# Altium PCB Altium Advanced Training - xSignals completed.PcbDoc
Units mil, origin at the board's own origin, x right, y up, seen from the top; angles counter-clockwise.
Board outline 4055.12 x 2100 mil, 3 copper layers (Top Layer, GND, Bottom Layer), stack 68.617 mil thick; 14 components, 11 nets, 32 pads, 2 vias.
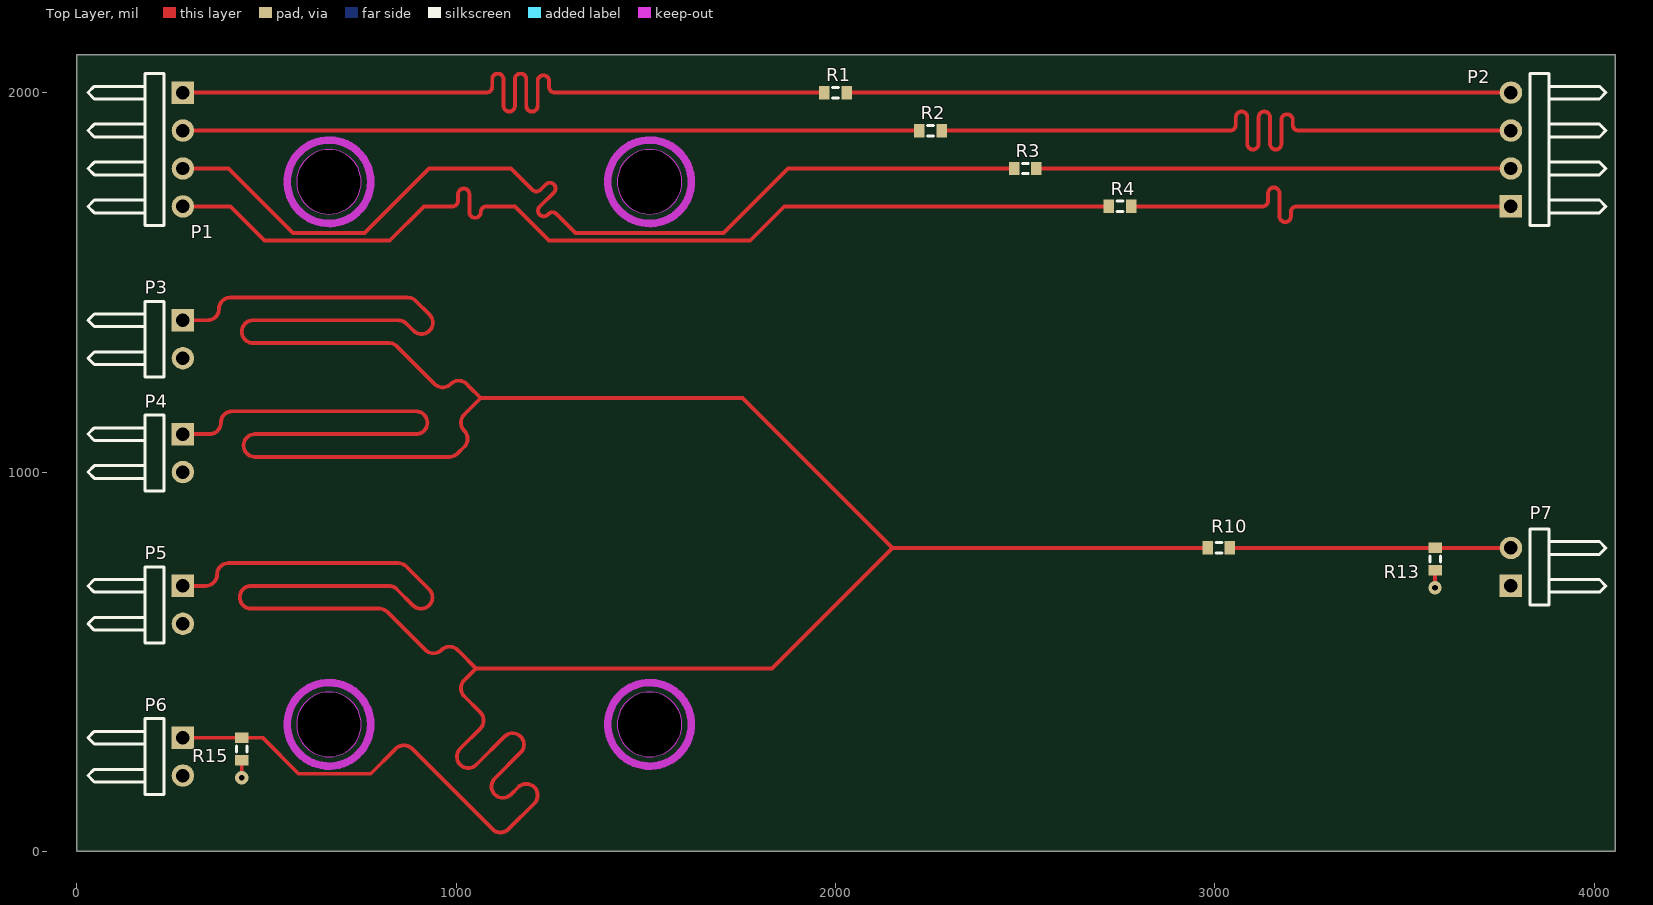
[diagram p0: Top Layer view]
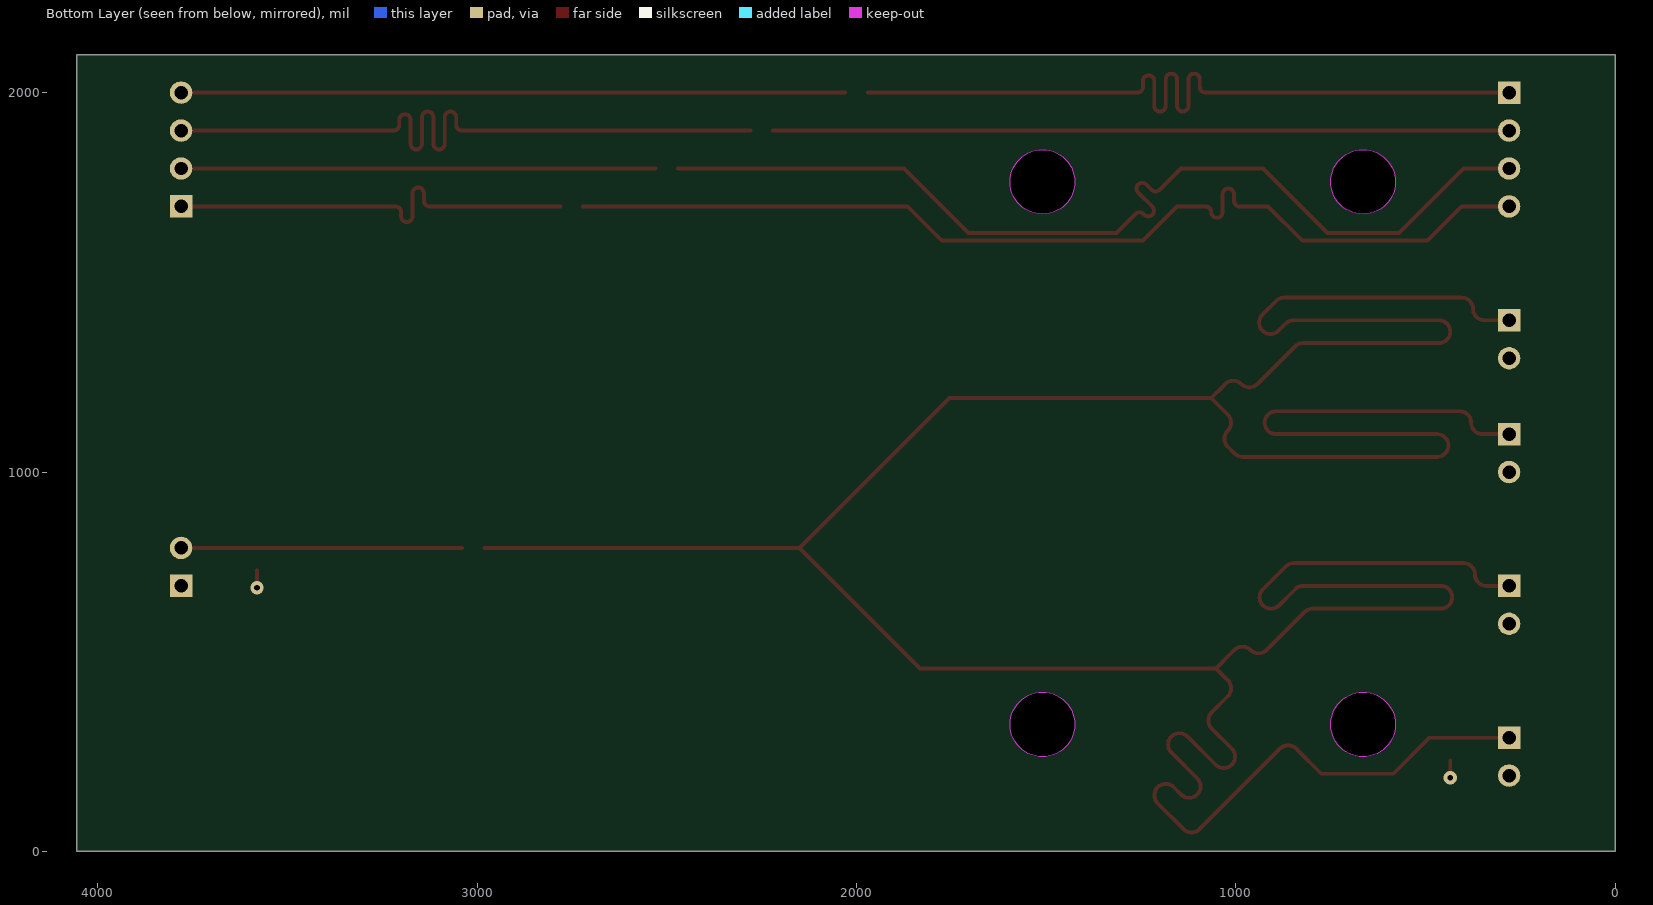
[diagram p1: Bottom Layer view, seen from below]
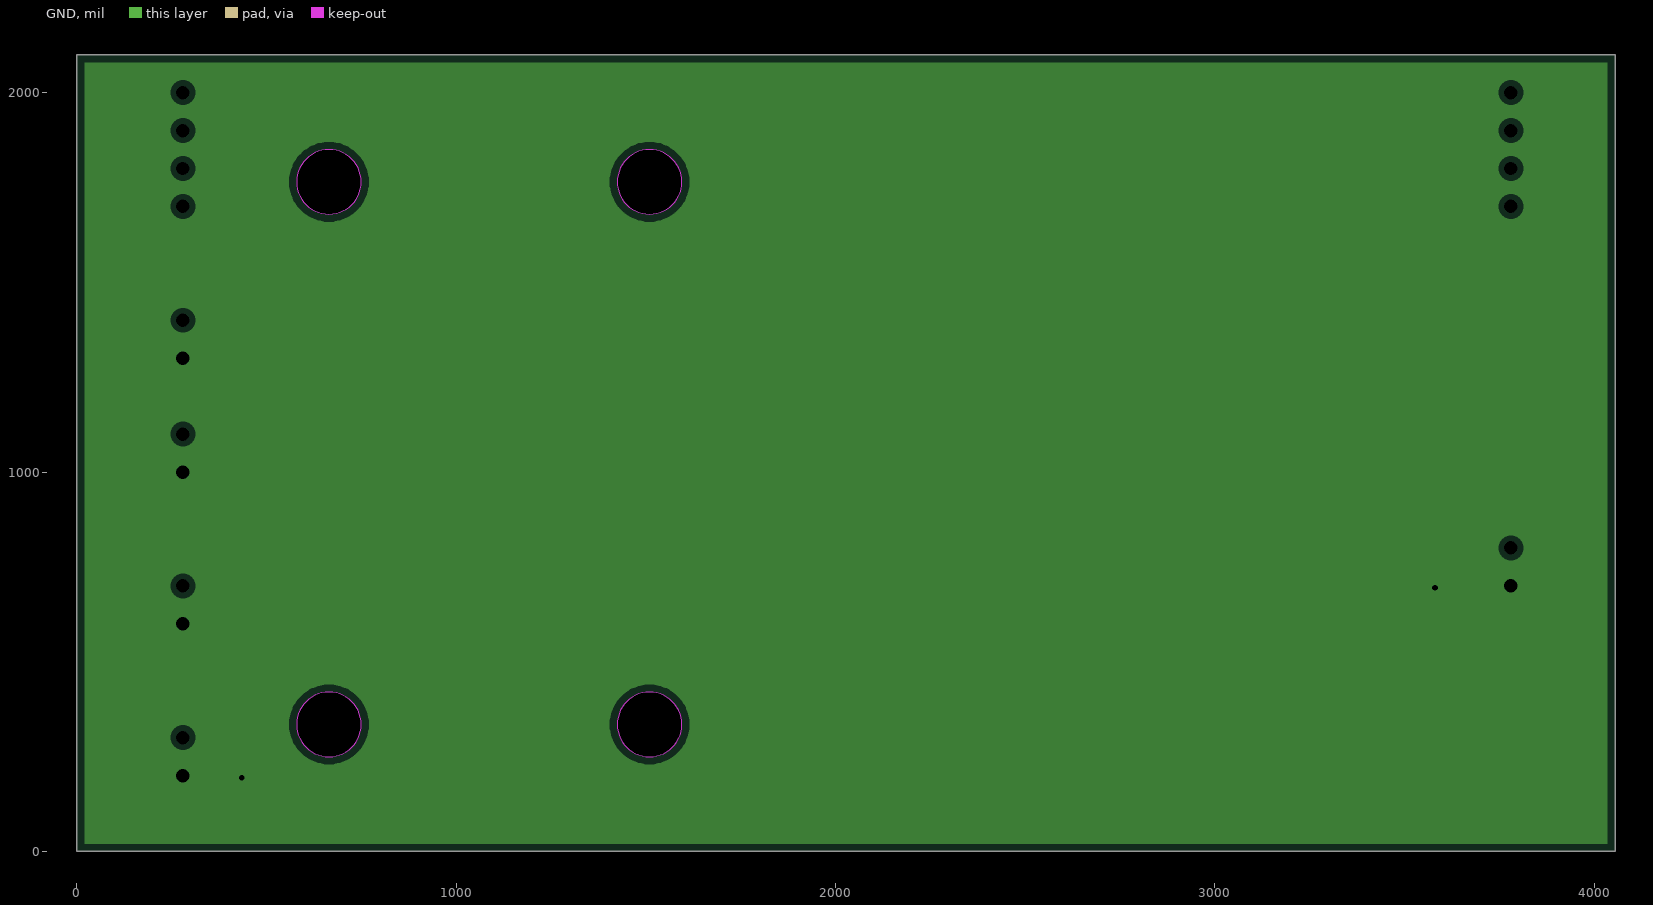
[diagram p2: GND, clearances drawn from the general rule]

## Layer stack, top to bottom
Top Solder: solder mask 0.4, Solder Resist, Dk 3.5
Top Layer: signal copper 1.4
Dielectric1: core 59.4, FR-4, Dk 4
GND: plane copper 1.417, net GND
Dielectric 2: prepreg 5, Dk 4.2
Bottom Layer: signal copper 1.4
Bottom Solder: solder mask 0.4, Solder Resist, Dk 3.5

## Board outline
0,0 4055.12,0 4055.12,2100 0,2100
cut-out: 579.65,334.79 ccw(c664.79,334.79) 664.79,249.65 ccw(c664.79,334.79) 749.94,334.79 ccw(c664.79,334.79) 664.79,419.94 ccw(c664.79,334.79)
cut-out: 579.65,1764.79 ccw(c664.79,1764.79) 664.79,1679.65 ccw(c664.79,1764.79) 749.94,1764.79 ccw(c664.79,1764.79) 664.79,1849.94 ccw(c664.79,1764.79)
cut-out: 1424.65,334.79 ccw(c1509.79,334.79) 1509.79,249.65 ccw(c1509.79,334.79) 1594.94,334.79 ccw(c1509.79,334.79) 1509.79,419.94 ccw(c1509.79,334.79)
cut-out: 1424.65,1764.79 ccw(c1509.79,1764.79) 1509.79,1679.65 ccw(c1509.79,1764.79) 1594.94,1764.79 ccw(c1509.79,1764.79) 1509.79,1849.94 ccw(c1509.79,1764.79)

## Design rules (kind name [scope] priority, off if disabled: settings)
AcuteAngle [All] p1: minimum=5.50000000000000E+0001 checktracksonly=FALSE
AssemblyTestPointUsage [All] p1 off:
AssemblyTestpoint [All] p1 off: testpointundercomponent=TRUE minsize=40 maxsize=100 preferedsize=60 minholesize=0 maxholesize=40 preferedholesize=32 testpointgrid=1 usegrid=TRUE gridtolerance=0.01 allowsidetop=TRUE allowsidebottom=TRUE
BoardOutlineClearance [All] p1: gap=10 ignorepadtopadclearanceinfootprint=FALSE except(0: Arc-SplitContinuation Track-SplitContinuation SMDPad-SplitContinuation THPad-SplitContinuation Via-SplitContinuation Fill-SplitContinuation Poly-SplitContinuation Region-SplitContinuation Text-SplitContinuation)
Clearance [All] p1: gap=8 ignorepadtopadclearanceinfootprint=FALSE except(0: Arc-Hole Track-Hole SMDPad-Hole THPad-Hole Via-Hole Fill-Hole Poly-Hole Region-Hole Text-Hole)
FabricationTestPointUsage [All] p1 off: valid=0 allowmultiple=FALSE
FabricationTestpoint [(IsPad And (OnTopLayer Or OnBottomLayer))] p1 off: side=3 testpointundercomponent=TRUE minsize=40 maxsize=100 preferedsize=60 minholesize=0 maxholesize=40 preferedholesize=32 testpointgrid=1 allowsidetop=TRUE allowsidebottom=TRUE usegrid=TRUE gridtolerance=0.01
Height [All] p1: minheight=0 maxheight=1500 prefheight=500
HoleSize [All] p1: absolutevalues=TRUE maxlimit=200 minlimit=10 maxpercent=80.000 minpercent=20.000
HoleToHoleClearance [All] p1: gap=1 allowstackedmicrovias=FALSE
Length Length_TJunct [InxSignalClass('xSignals_R10_P3,P4,P5,P6')] p1: maxlimit=4100 minlimit=3900
Length Length_Series-Term [InxSignalClass('Series-Term')] p2: maxlimit=3855 minlimit=3845
MatchedLengths MatchLengths_xSignals_R10_P3,P4,P5,P6 [InxSignalClass('xSignals_R10_P3,P4,P5,P6_MatchLengthsClass')] p1: tolerance=20 checknetsindiffpair=FALSE checkdiffpairvsdiffpair=TRUE checkxsignals=TRUE checkothers=TRUE
MinimumAnnularRing [All] p1: minimumring=5
MinimumSolderMaskSliver [All] p1: minsoldermaskwidth=3
NetAntennae [All] p1: netantennaetolerance=5
PlaneClearance [All] p1: clearance=15
PlaneConnect [All] p1: planeconnectstyle=Relief reliefexpansion=15 reliefentries=4 reliefconductorwidth=8 reliefairgap=8
PolygonConnect [All] p1: connectstyle=Relief reliefconductorwidth=8 reliefentries=4 polygonreliefangle="90 Angle" airgapwidth=10
RoutingTopology RoutingTopology_TJUNCT [InNet('TJUNCT')] p1: topology=Starburst
RoutingTopology [All] p2: topology=Shortest
RoutingVias [All] p1: holewidth=10 width=20 viastyle="Through Hole" minholewidth=10 minwidth=20 maxholewidth=30 maxwidth=40
SilkToSilkClearance [All] p1: silktosilkclearance=1
SilkToSolderMaskClearance SilkscreenOverComponentPads [IsPad] p1: minsilkscreentomaskgap=2 clearancetoexposedcopper=TRUE
SolderMaskExpansion [All] p1: expansion=1 istentingtop=FALSE
Width [All] p1: maxlimit=200 minlimit=8 preferedwidth=10
16 further rules are at their usual default settings.

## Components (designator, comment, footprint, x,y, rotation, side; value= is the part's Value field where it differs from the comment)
P1 "Header 4H" HDR1X4H 280,2000 r270 top
P2 "Header 4H" HDR1X4H 3780,1700 r90 top
P3 "Header 2H" HDR1X2H 280,1400 r270 top
P4 "Header 2H" HDR1X2H 280,1100 r270 top
P5 "Header 2H" HDR1X2H 280,700 r270 top
P6 "Header 2H" HDR1X2H 280,300 r270 top
P7 "Header 2H" HDR1X2H 3780,700 r90 top
R1 "Res3" J1-0603 2000,2000 r180 top
R2 "Res3" J1-0603 2250,1900 r180 top
R3 "Res3" J1-0603 2500,1800 r180 top
R4 "Res3" J1-0603 2750,1700 r180 top
R10 "Res3" J1-0603 3010,800 r180 top
R13 "Res3" J1-0603 3580,770.47 r90 top
R15 "Res3" J1-0603 435,270 r90 top

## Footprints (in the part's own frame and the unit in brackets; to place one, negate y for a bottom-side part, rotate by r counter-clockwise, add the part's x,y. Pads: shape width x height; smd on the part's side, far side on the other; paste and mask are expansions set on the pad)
HDR1X2H [mm] "Connector; Header; 2 Position; Right Angle"
  rect 1.5x1.5 hole 0.9: 1(0,0)
  round 1.5 hole 0.9: 2(2.54,0)
  silkscreen extent -1.27,-6.35 3.81,-1.27
HDR1X4H [mm] "Connector; Header; 4 Position; Right Angle"
  rect 1.5x1.5 hole 0.9: 1(0,0)
  round 1.5 hole 0.9: 2(2.54,0) 3(5.08,0) 4(7.62,0)
  silkscreen extent -1.27,-6.35 8.89,-1.27
J1-0603 [mm] "Chip Resistor, Body 1.6x0.8mm, IPC High Density"
  rect 0.7x0.9 smd: 1(-0.75,0) 2(0.75,0)
  silkscreen extent -0.2,-0.35 0.2,0.35, body extent -0.85,-0.48 0.85,0.48, height 0.9

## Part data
P1 P2: "Header, 4-Pin, Right Angle"
P3 P4 P5 P6 P7: "Header, 2-Pin, Right Angle"
R1 R2 R3 R4 R10 R13 R15: "Resistor"

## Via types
v1: diameter 35, hole 15, Top Layer to Bottom Layer, 2 vias

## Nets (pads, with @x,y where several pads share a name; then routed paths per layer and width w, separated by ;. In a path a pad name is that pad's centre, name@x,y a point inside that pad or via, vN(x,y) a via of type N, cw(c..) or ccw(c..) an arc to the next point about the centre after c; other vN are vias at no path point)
BUS1: P1.1 R1.2 | length 2104.5
  Top Layer w10: P1.1 1050,2000 1075,2000 1080,2000 ccw(c1080,2015) 1095,2015 1095,2035 cw(c1110,2035) 1125,2035 1125,1965 ccw(c1140,1965) 1155,1965 1155,2035 cw(c1170,2035) 1185,2035 1185,1965 ccw(c1200,1965) 1215,1965 1215,2030.66 cw(c1230,2030.66) 1245,2030.66 1245,2015 ccw(c1260,2015) 1260,2000 1565,2000 1569.77,2000 R1.2
BUS2: P1.2 R2.2 | length 1940.5
  Top Layer w10: P1.2 R2.2
BUS3: P1.3 R3.2 | length 2599.5
  Top Layer w10: P1.3 400,1800 570,1630 758.75,1630 928.75,1800 1145,1800 1197.5,1747.5 1201.04,1743.96 ccw(c1211.64,1754.57) 1222.25,1743.96 1236.39,1758.11 cw(c1247,1747.5) 1257.6,1758.11 cw(c1247,1747.5) 1257.6,1736.89 1220.12,1699.41 ccw(c1230.73,1688.8) 1220.12,1678.2 ccw(c1230.73,1688.8) 1241.33,1678.2 1243.46,1680.32 cw(c1254.07,1669.72) 1264.68,1680.32 1315,1630 1705,1630 1875,1800 1937.5,1800 2235,1800 2285,1800 R3.2
BUS4: P1.4 R4.2 | length 2705.6
  Top Layer w10: P1.4 405,1700 495,1610 825,1610 915,1700 985,1700 990,1700 ccw(c990,1715) 1005,1715 1005,1732.3 cw(c1020,1732.3) 1035,1732.3 1035,1685 ccw(c1050,1685) 1065,1685 cw(c1080,1685) 1080,1700 1149.63,1700 1155,1700 1245,1610 1775,1610 1865,1700 R4.2
GND: P3.2 P4.2 P5.2 P6.2 P7.1 R13.1 R15.1 | length 91.9
  Top Layer w10: v1(435,194.53) R15.1 ; v1(3580,695) R13.1
OBUS1: P2.4 R1.1 | length 1750.5
  Top Layer w10: R1.1 2897.82,2000 P2.4
OBUS2: P2.3 R2.1 | length 1909.5
  Top Layer w10: R2.1 2540,1900 2720,1900 3035,1900 3040,1900 ccw(c3040,1915) 3055,1915 3055,1935 cw(c3070,1935) 3085,1935 3085,1865 ccw(c3100,1865) 3115,1865 3115,1935 cw(c3130,1935) 3145,1935 3145,1865 ccw(c3160,1865) 3175,1865 3175,1928.16 cw(c3190,1928.16) 3205,1928.16 3205,1915 ccw(c3220,1915) 3220,1900 3395,1900 P2.3
OBUS3: P2.2 R3.1 | length 1250.5
  Top Layer w10: R3.1 P2.2
OBUS4: P2.1 R4.1 | length 1144.4
  Top Layer w10: R4.1 3120,1700 3125,1700 ccw(c3125,1715) 3140,1715 3140,1735 cw(c3155,1735) 3170,1735 3170,1673.71 ccw(c3185,1673.71) 3200,1673.71 3200,1685 cw(c3215,1685) 3215,1700 3271.89,1700 3300,1700 P2.1
TJSOURCE: P7.2 R10.1 R13.2 | length 740.5
  Top Layer w10: R10.1 R13.2 P7.2
TJUNCT: P3.1 P4.1 P5.1 P6.1 R10.2 R15.2 | length 11285.9
  Top Layer w10: P6.1 434.53,300 R15.2 435.47,300 490,300 585,205 775,205 837.5,267.5 841.04,271.04 cw(c862.25,249.82) 883.46,271.04 1095.59,58.9 ccw(c1116.81,80.12) 1138.01,58.89 1206.01,126.89 ccw(c1184.8,148.11) 1206.01,169.32 ccw(c1184.8,148.11) 1163.58,169.32 1144.41,150.15 cw(c1123.2,171.36) 1101.98,150.15 cw(c1123.2,171.36) 1101.98,192.57 1169.96,260.55 ccw(c1148.74,281.76) 1169.96,302.97 ccw(c1148.74,281.76) 1127.53,302.97 1053.16,228.6 cw(c1031.95,249.82) 1010.73,271.02 1063.9,324.2 ccw(c1042.68,345.4) 1063.9,366.6 1021.46,409.04 cw(c1042.68,430.25) 1021.46,451.46 1025,455 1052.5,482.5 ; P5.1 335,700 340,700 ccw(c340,730) 370,730 cw(c400,730) 400,760 847.43,760 cw(c847.43,730) 868.63,751.23 928.88,690.97 cw(c907.67,669.76) 928.88,648.55 cw(c907.67,669.76) 886.45,648.55 843.77,691.23 ccw(c822.57,670) 822.57,700 460,700 ccw(c460,670) 430,670 ccw(c460,670) 460,640 797.72,640 cw(c797.72,610) 818.92,631.23 919.11,531.04 ccw(c940.32,552.25) 961.55,531.05 cw(c982.75,509.82) 1003.96,531.04 1007.5,527.5 1052.5,482.5 ; P4.1 345,1100 350,1100 ccw(c350,1130) 380,1130 cw(c410,1130) 410,1160 894.28,1160 cw(c894.28,1130) 924.28,1130 cw(c894.28,1130) 894.28,1100 470,1100 ccw(c470,1070) 440,1070 ccw(c470,1070) 470,1040 982.43,1040 ccw(c982.43,1070) 1003.63,1048.77 1021.48,1066.62 ccw(c1000.25,1087.82) 1021.43,1109.07 cw(c1042.68,1130.25) 1021.46,1151.46 1025,1155 1065,1195 ; P3.1 340,1400 345,1400 ccw(c345,1430) 375,1430 cw(c405,1430) 405,1460 872.43,1460 cw(c872.43,1430) 893.63,1451.23 930,1414.86 cw(c908.78,1393.64) 930,1372.43 cw(c908.78,1393.64) 887.57,1372.43 868.77,1391.23 ccw(c847.57,1370) 847.57,1400 465,1400 ccw(c465,1370) 435,1370 ccw(c465,1370) 465,1340 822.72,1340 cw(c822.72,1310) 843.92,1331.23 943.18,1231.96 ccw(c964.4,1253.18) 985.62,1231.98 cw(c1006.82,1210.75) 1028.04,1231.96 1031.57,1228.43 1065,1195 ; R10.2 2150,800 ; 1052.5,482.5 1832.5,482.5 2150,800 ; 1065,1195 1755,1195 2150,800

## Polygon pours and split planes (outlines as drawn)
GND on GND (split plane): 4035.02,20.1 20.1,20.1 20.1,2079.9 4035.02,2079.9

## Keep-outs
Top Layer:
  circle w20: c665,335 r110
  circle w20: c665,1765 r110
  circle w20: c1510,335 r110
  circle w20: c1510,1765 r110

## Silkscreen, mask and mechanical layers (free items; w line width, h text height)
Top Overlay:
  text "Altium Advanced Training: '.Pcb_File_Name_No_Path'" at 15,-251.68 h100
Mechanical 1:
  drawing of 211 lines, arcs and shapes, not listed
  text "Layer" at -5222.5,-212.5 h60
  text "Name" at -4874.26,-212.5 h60
  text "Material" at -4109.54,-212.5 h60
  text "Thickness" at -3447.08,-212.5 h60
  text "Constant" at -2933.16,-212.5 h60
  text "Board Layer Stack" at -2440.37,-212.5 h60
  text "Top Overlay" at -4874.26,-332.5 h60
  text "Top Solder" at -4874.26,-452.5 h60
  text "Solder Resist" at -4109.54,-452.5 h60
  text "0,40mil" at -3447.08,-452.5 h60
  text "3.5" at -2933.16,-452.5 h60
  text "1" at -5222.5,-572.5 h60
  text "Top Layer" at -4874.26,-572.5 h60
  text "1,40mil" at -3447.08,-572.5 h60
  text "Dielectric1" at -4874.26,-692.5 h60
  text "FR-4" at -4109.54,-692.5 h60
  text "59,40mil" at -3447.08,-692.5 h60
  text "4" at -2933.16,-692.5 h60
  text "2" at -5222.5,-812.5 h60
  text "GND" at -4874.26,-812.5 h60
  text "1,42mil" at -3447.08,-812.5 h60
  text "Dielectric 2" at -4874.26,-932.5 h60
  text "5,00mil" at -3447.08,-932.5 h60
  text "4.2" at -2933.16,-932.5 h60
  text "3" at -5222.5,-1052.5 h60
  text "Bottom Layer" at -4874.26,-1052.5 h60
  text "1,40mil" at -3447.08,-1052.5 h60
  text "Bottom Solder" at -4874.26,-1172.5 h60
  text "Solder Resist" at -4109.54,-1172.5 h60
  text "0,40mil" at -3447.08,-1172.5 h60
  text "3.5" at -2933.16,-1172.5 h60
  text "Bottom Overlay" at -4874.26,-1292.5 h60
Mechanical 16:
  lines w5: -5810.13,-1827.43 -5610.13,-1827.43 ; -5810.13,547.57 -5610.13,547.57 ; -5810.13,2922.57 -5610.13,2922.57 ; -3310.13,-4202.43 -3310.13,-4002.43 ; -3310.13,5097.57 -3310.13,5297.57 ; -810.13,-4202.43 -810.13,-4002.43 ; -810.13,5097.57 -810.13,5297.57 ; 1536.87,-4002.43 1536.87,-3207.43 ; 1689.87,-4202.43 1689.87,-4002.43 ; 1689.87,5097.57 1689.87,5297.57 ; 3089.87,-3207.43 1536.87,-3207.43 ; 3089.87,-2934.43 1536.87,-2934.43 1536.87,-3207.43 ; 4189.87,-4202.43 4189.87,-4002.43 ; 4189.87,5097.57 4189.87,5297.57 ; 4489.87,-3702.43 8989.87,-3702.43 ; 4489.87,-3402.43 8989.87,-3402.43 ; 4489.87,-3102.43 5989.87,-3102.43 ; 5989.72,-4002.28 5989.72,-3402.28 5989.72,-2802.28 8989.72,-2802.28 8989.72,-4002.28 ; 5989.87,-2802.43 4489.87,-2802.43 ; 6613.21,-4202.75 6613.21,-4002.75 ; 6689.87,-4202.43 6689.87,-4002.43 ; 6689.87,5097.57 6689.87,5297.57 ; 7259.72,-4002.28 7259.72,-3702.28 ; 8089.72,-4002.28 8089.72,-3402.28 ; 8989.87,-1827.43 9189.87,-1827.43 ; 8989.87,547.57 9189.87,547.57 ; 8989.87,2922.57 9189.87,2922.57 ; 4489.87,-4002.43 4489.87,-2802.43 ; 4489.87,-4002.43 8989.87,-4002.43 ; 4489.87,-4002.43 3089.87,-4002.43 3089.87,-2802.43 4489.87,-2802.43 ; 8989.87,-4002.43 8989.87,5097.57 -5610.13,5097.57 -5610.13,-4002.43 8989.87,-4002.43 ; -5810.13,-4202.43 -5810.13,5297.57 9189.87,5297.57 9189.87,-4202.43 -5810.13,-4202.43
  lines w10: 6539.87,4817.57 6539.87,4892.57 6539.87,4957.57 6539.87,5032.57 6539.87,5097.57 ; 6540,4817.57 8989.87,4817.57 ; 6540,4892.57 8989.87,4892.57 8989.87,5032.57 ; 6540,4957.57 8989.87,4957.57 ; 6540,5032.57 8989.87,5032.57 ; 6540,5097.57 8989.87,5097.57 8989.87,5032.57 ; 6684.87,4817.76 6684.87,5032.57 ; 7014.87,4817.76 7014.87,5032.57 ; 8419.87,4817.76 8419.87,5032.57 ; 8689.87,4817.76 8689.87,5032.57
  text "1" at -4578.79,5167.57 h70
  text "2" at -2083.13,5167.57 h70
  text "3" at 406.21,5167.57 h70
  text "4" at 2912.88,5167.57 h70
  text "5" at 5411.87,5167.57 h70
  text "6" at 7916.87,5167.57 h70
  text "REVISIONS" at 7642,5051.76 h30
  text "DESCRIPTION" at 7630,4980.76 h30
  text "REV" at 6564.87,4977.57 h30
  text "ECO#/ECR#" at 6724.87,4977.57 h30
  text "APPROV" at 8454.87,4977.57 h30
  text "DATE" at 8794.87,4977.57 h30
  text "01" at 6584.87,4912.57 h30
  text "INITIAL RELEASE" at 7054.87,4912.57 h30
  text "10/31/11" at 8734.87,4912.57 h30
  text "A" at -5735.13,4024.57 h70
  text "A" at 9064.87,4024.57 h70
  text "B" at -5735.13,1644.57 h70
  text "B" at 9064.87,1644.57 h70
  text "C" at -5735.13,-730.43 h70
  text "C" at 9064.87,-730.43 h70
  text "ENGINEER:" at 4539.87,-2902.43 h45
  text "TITLE:" at 6039.72,-2902.28 h45
  text "<YOUR NAME>" at 4646.87,-3053.43 h80
  text "Company" at 3158,-3074.24 h140
  text "D" at -5735.13,-3100.43 h70
  text "D" at 9064.87,-3100.43 h70
  text "PCB DESIGNER:" at 4539.87,-3197.43 h45
  text "UNLESS OTHERWISE SPECIFIED" at 1626.87,-3313.43 h55.31
  text "<YOUR NAME>" at 4644.87,-3376.43 h80
  text "DIMINSIONS ARE IN INCHES." at 1626.87,-3401.43 h55.31
  text "LAYER" at 6040.72,-3475.28 h45
  text "DATE:" at 4539.87,-3502.43 h45
  text "REV:" at 8139.72,-3502.28 h45
  text "TOLERANCES ARE:" at 1954.87,-3580.43 h55.31
  text ".PRINT_DATE" at 4589.87,-3622.43 h70
  text "01" at 8474.72,-3636.3 h130
  text "100 Main Street" at 3126.5,-3638.02 h56.25
  text "DECIMALS" at 1616.87,-3704.43 h55.31
  text "ANGLES" at 2576.87,-3720.43 h55.31
  text "AnytownUSA, CA 12345" at 3124.37,-3734.35 h56.25
  text "SHT NO:" at 7280.72,-3792.28 h45
  text ".XX  +/- .01" at 1612.87,-3800.43 h55.31
  text "FILE NAME:" at 4539.87,-3802.43 h45
  text "DWG NO:" at 6039.72,-3802.28 h45
  text "SCALE:" at 8139.72,-3802.28 h45
  text "+/- .5 DEG" at 2456.87,-3817.43 h55.31
  text "Phone: (123) 555-1212" at 3122.21,-3832.82 h55.31
  text ".XXX +/- .003" at 1612.87,-3906.43 h55.31
  text "name@company.com" at 3122.21,-3914.2 h56.25
  text ".PCB_FILE_NAME_NO_PATH" at 4589.83,-3922.38 h70
  text ".PCB_FILE_NAME_NO_PATH" at 4589.87,-3922.43 h70
  text "N/A" at 8414.72,-3926.28 h130
  text "of" at 7661.67,-3949.61 h75
  text "1" at -4578.79,-4132.43 h70
  text "2" at -2083.13,-4132.43 h70
  text "3" at 406.21,-4132.43 h70
  text "4" at 2912.88,-4132.43 h70
  text "5" at 5411.87,-4132.43 h70
  text "4" at 7916.72,-4132.28 h70
Drill Drawing:
  circle w10: c-5248.98,-3104.28 r26.94
  lines w10: -5275.92,-3252.42 -5222.05,-3252.42 -5222.05,-3198.55 -5275.92,-3198.55 -5275.92,-3252.42
  lines w15: -5324.83,-3288.79 1089.13,-3288.79 ; -5324.83,-3046.36 1089.13,-3046.36 ; -4873.54,-3410 -4873.54,-2925.15 ; -4433.45,-3410 -4433.45,-2925.15 ; -3524.83,-3410 -3524.83,-2925.15 ; -3109.91,-3410 -3109.91,-2925.15 ; -2510.8,-3410 -2510.8,-2925.15 ; -1295.21,-3410 -1295.21,-2925.15 ; -812.42,-3410 -812.42,-2925.15 ; -203.62,-3410 -203.62,-2925.15 ; 453.65,-3410 453.65,-2925.15 ; -5324.83,-3410 1089.13,-3410 1089.13,-2925.15 -5324.83,-2925.15 -5324.83,-3410
  text "Symbol" at -5252.11,-3010 h58.18
  text "Count" at -4837.18,-3010 h58.18
  text "Hole Size" at -4397.09,-3010 h58.18
  text "Plated" at -3488.47,-3010 h58.18
  text "Hole Type" at -3073.54,-3010 h58.18
  text "Drill Layer Pair" at -2474.43,-3010 h58.18
  text "Via/Pad" at -1258.84,-3010 h58.18
  text "Pad Shape" at -776.06,-3010 h58.18
  text "Technology" at -167.26,-3010 h58.18
  text "Tolerance" at 490.02,-3010 h58.18
  text "2" at -4837.18,-3131.21 h48.48
  text "15,00mil (0,381mm)" at -4397.09,-3131.21 h48.48
  text "PTH" at -3488.47,-3131.21 h48.48
  text "Round" at -3073.54,-3131.21 h48.48
  text "Top Layer - Bottom Layer" at -2474.43,-3131.21 h48.48
  text "Via" at -1258.84,-3131.21 h48.48
  text "Rounded" at -776.06,-3131.21 h48.48
  text "v89h38" at -167.26,-3131.21 h48.48
  text "18" at -4837.18,-3252.42 h48.48
  text "35,43mil (0,900mm)" at -4397.09,-3252.42 h48.48
  text "PTH" at -3488.47,-3252.42 h48.48
  text "Round" at -3073.54,-3252.42 h48.48
  text "Top Layer - Bottom Layer" at -2474.43,-3252.42 h48.48
  text "Pad" at -1258.84,-3252.42 h48.48
  text "(Mixed)" at -776.06,-3252.42 h48.48
  text "(Mixed)" at -167.26,-3252.42 h48.48
  text "20 Total" at -4837.18,-3373.63 h48.48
